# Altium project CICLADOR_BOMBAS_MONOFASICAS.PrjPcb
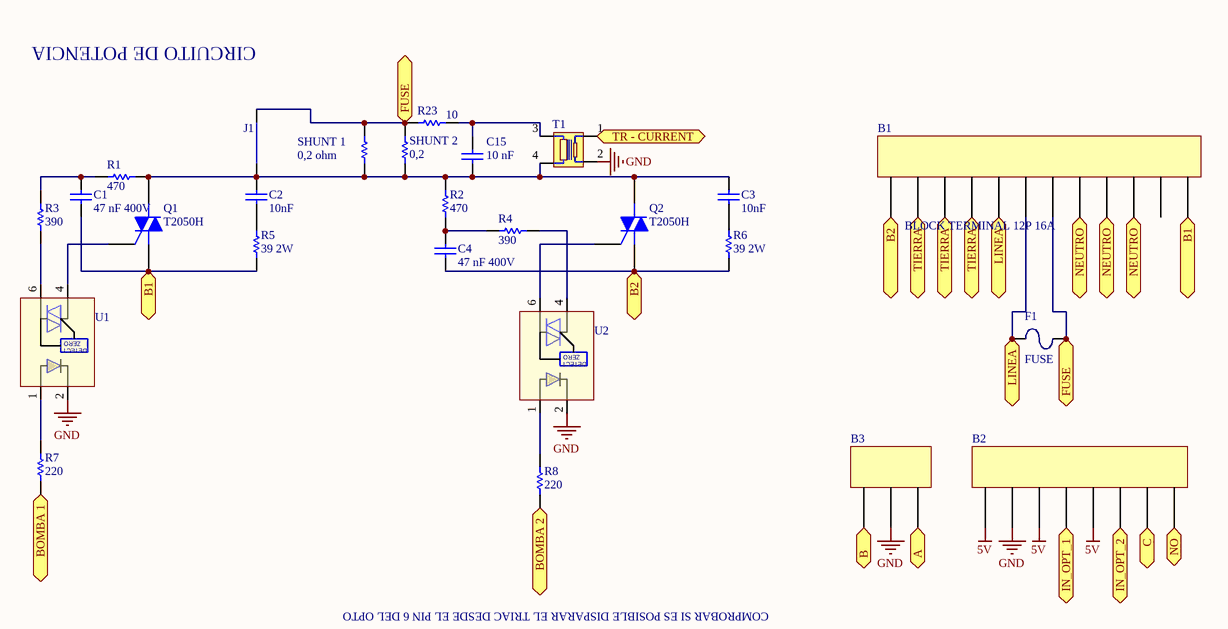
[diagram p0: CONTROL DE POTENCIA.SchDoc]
3 sheets, 80 parts. Net scope: flat (ports and power ports of the same name join across sheets).
Board file: PCB_BOARD_01.PcbDoc
Sheets:
  CONTROL DE POTENCIA.SchDoc
  MCU.SchDoc
  SPERIFERICOS.SchDoc

## Sheet CONTROL DE POTENCIA.SchDoc
size A4

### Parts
B1  BLOCK TERMINAL 12P 16A  [BLOCK TERMINAL 12P 16A]
B2  BLOCK TERMINAL 12P 16A  [BORNERA 8P 2.5MM 2A]  (value not drawn)
B3  BORNERA 3P  [BORNERA_ENCASTRE]  (value not drawn)
C1  value 47 nF 400V  [VP60-3.6]  (hidden comment: 47 nF  400V)
C2  10nF  [VP60-3.6]
C3  10nF  [VP60-3.6]
C4  value 47 nF 400V  [VP60-3.6]  (hidden comment: 47 nF  400V)
C15  10 nF  [0805]
F1  FUSE  [VP45-3.2]
J1  JUMPER  [JUMPER 10MM]  (value not drawn)
Q1  T2050H  [TO254P1280-3_4M]
Q2  T2050H  [TO254P1280-3_4M]
R1  470  [ERA-0805]
R2  470  [ERA-0805]
R3  390  [ERA-0805]
R4  390  [ERA-0805]
R5  39 2W  [R12x4]
R6  39 2W  [R12x4]
R7  220  [ERA-0805]
R8  220  [ERA-0805]
R23  10  [ERA-0805]
SHUNT_1  0,2 ohm  [M1WS-2512]
SHUNT_2  0,2  [M1WS-2512]
T1  TRANSFORMADOR  [TRANSFORMADOR TRANSMISION DE DATOS]  (value not drawn)
U1  MOC3041  [DIP_6]  (value not drawn)
U2  MOC3041  [DIP_6]  (value not drawn)

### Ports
A, B, B1, B2, BOMBA 1, BOMBA 2, C, FUSE, IN_OPT_1, IN_OPT_2, LINEA, NEUTRO, NO, TIERRA, TR - CURRENT

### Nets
5V: B2.4 B2.6 B2.8
GND: B2.7 B3.2 T1.2 U1.2 U2.2
NetB1_1: B1.1 C1.1 Q1.1(M1) R5.1 ; port B1
NetB1_3: B1.3 B1.4 B1.5 ; port NEUTRO
NetB1_6: B1.6 F1.2 J1.2 R23.2 SHUNT_1.1 SHUNT_2.1 ; port FUSE
NetB1_7: B1.7 B1.8 F1.1 ; port LINEA
NetB1_9: B1.9 B1.10 B1.11 ; port TIERRA
NetB1_12: B1.12 C4.1 Q2.1(M1) R6.1 ; port B2
NetB2_1: B2.1 ; port NO
NetB2_2: B2.2 ; port C
NetB2_3: B2.3 ; port IN_OPT_2
NetB2_5: B2.5 ; port IN_OPT_1
NetB3_1: B3.1 ; port A
NetB3_3: B3.3 ; port B
NetC1_2: C1.2 R1.2 R3.1
NetC2_1: C2.1 R5.2
NetC2_2: C2.2 C3.2 C15.1 J1.1 Q1.2(M2) Q2.2(M2) R1.1 R2.1 SHUNT_1.2 SHUNT_2.2 T1.4
NetC3_1: C3.1 R6.2
NetC4_2: C4.2 R2.2 R4.1
NetC15_2: C15.2 R23.1 T1.3
NetL2_2: T1.1 ; port TR - CURRENT
NetQ1_3: Q1.3(G) U1.4
NetQ2_3: Q2.3(G) U2.6
NetR3_2: R3.2 U1.6
NetR4_2: R4.2 U2.4
NetR7_1: R7.1 ; port BOMBA 1
NetR7_2: R7.2 U1.1
NetR8_1: R8.1 ; port BOMBA 2
NetR8_2: R8.2 U2.1

Not connected (* = marked no-connect by the designer): B1 2

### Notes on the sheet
- CIRCUITO DE POTENCIA
- COMPROBAR SI ES POSIBLE DISPARAR EL TRIAC DESDE EL PIN 6 DEL OPTO

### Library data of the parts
C1 C4 = C0805: Ceramic Chip Capacitor - Standard; Note: Footprint corresponds to dimensions for bulk cassette packaging. This case size has tightened tolerances.
C2 C3 = VP52BA102GC: Dipped Radial Multilayer Ceramic Capacitor COG (NPO): 1000pF, 200V; Provider: Mouser
C15 = C0805: Ceramic Chip Capacitor - Standard; Note: Footprint corresponds to dimensions for bulk cassette packaging. This case size has tightened tolerances.; Value: 100nF
F1 = FUSE: Fusible 0697H9200-02 - 20A Slow
J1 = JUMPER: PUENTE
Q1 Q2 = Q8025R5: Triac (25.0 Amps); pin to pad: 2>4
R1-R4 R7 R8 R23 = ERAS: Metal Film Thermosensitive Chip Resistor, 0.56 Ohm to 10k Ohm Range, 5% Tolerance, 0805 Size, 0.1 W; Note: If flow soldering, adjust pad width of PCB Footprint to 0.7 - 0.8 times the width of the resistor.
R5 R6 = ERG2: Metal Oxide Film Resistor, 0.1 Ohm to 100k Ohm Range, 2% and 5% Tolerance, 2 W
SHUNT_1 = ERAS: Metal Film Thermosensitive Chip Resistor, 0.56 Ohm to 10k Ohm Range, 5% Tolerance, 0805 Size, 0.1 W; Note: If flow soldering, adjust pad width of PCB Footprint to 0.7 - 0.8 times the width of the resistor.; Component: Resistor Shunt; Value: 470
SHUNT_2 = ERAS: Metal Film Thermosensitive Chip Resistor, 0.56 Ohm to 10k Ohm Range, 5% Tolerance, 0805 Size, 0.1 W; Note: If flow soldering, adjust pad width of PCB Footprint to 0.7 - 0.8 times the width of the resistor.; Value: 470
T1 = TRANSFORMADOR: pin to pad: 2>3 3>4 4>6
U1 U2 = MOC3021: OPTOACOPLADOR

## Sheet MCU.SchDoc
size A4
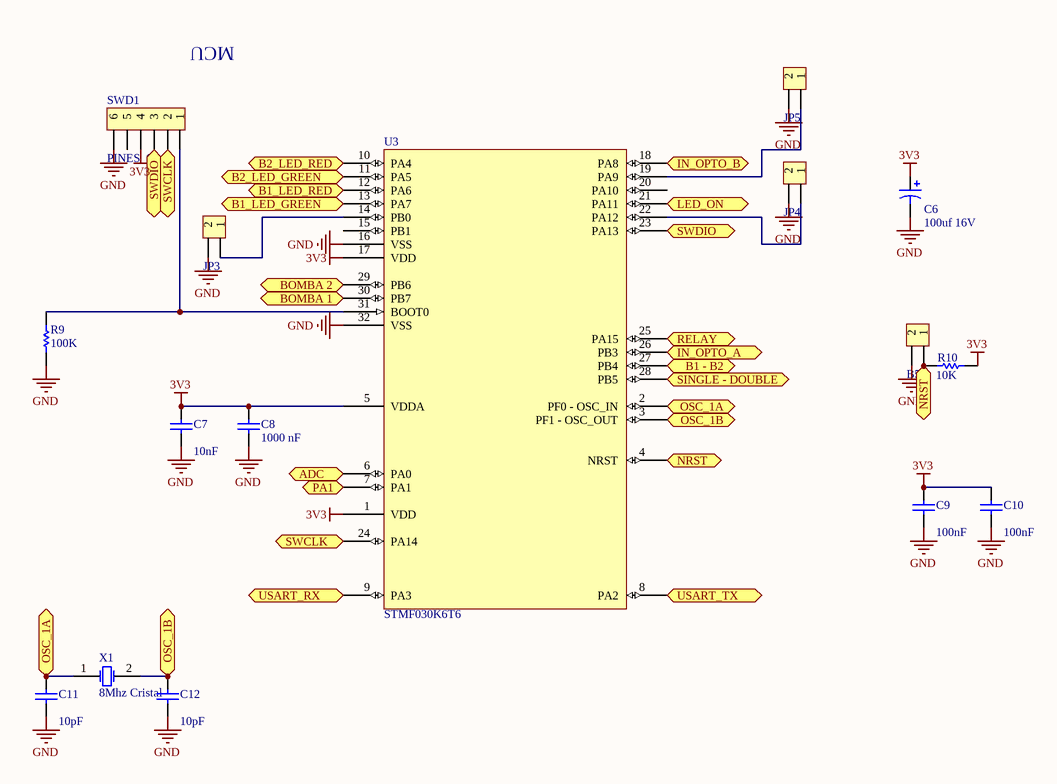
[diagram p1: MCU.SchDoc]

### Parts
B5  PINES_6  [PINES_2_2.54]  (value not drawn)
C6  100uf 16V  [CAPPR2-5X11]
C7  value 10nF  [0805]  (hidden comment: 10 nF)
C8  1000 nF  [0805]
C9  value 100nF  [0805]  (hidden comment: 100 nF)
C10  100nF  [0805]
C11  value 10pF  [0805]  (hidden comment: 10 pF)
C12  value 10pF  [0805]  (hidden comment: 10 pF)
JP3  PINES_6  [PINES_2_2.54]  (value not drawn)
JP4  PINES_6  [PINES_2_2.54]  (value not drawn)
JP5  PINES_6  [PINES_2_2.54]  (value not drawn)
R9  100K  [ERA-0805]
R10  10K  [ERA-0805]
SWD1  PINES_6  [PINES_6_2.54]
U3  STMF030K6T6  [LQFP_32]
X1  8Mhz Cristal  [HC49/4H_SMX]

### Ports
ADC, B1 - B2, B1_LED_GREEN, B1_LED_RED, B2_LED_GREEN, B2_LED_RED, BOMBA 1, BOMBA 2, IN_OPTO_A, IN_OPTO_B, LED_ON, NRST, OSC_1A, OSC_1B, PA1, RELAY, SINGLE - DOUBLE, SWCLK, SWDIO, USART_RX, USART_TX

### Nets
3V3: C6.1 C7.2 C8.2 C9.2 C10.2 R10.2 SWD1.4 U3.1(VDD) U3.5(VDDA) U3.17(VDD)
GND: B5.2 C6.2 C7.1 C8.1 C9.1 C10.1 C11.1 C12.1 JP3.2 JP4.2 JP5.2 R9.1 SWD1.6 U3.16(VSS) U3.32(VSS)
NetB5_1: B5.1 R10.1 U3.4(NRST) ; port NRST
NetC11_2: C11.2 U3.2(PF0_-_OSC_IN) X1.1(OSC1) ; port OSC_1A
NetC12_2: C12.2 U3.3(PF1_-_OSC_OUT) X1.2(OSC2) ; port OSC_1B
NetC13_2: U3.6(PA0) ; port ADC
NetJP1_1: U3.28(PB5) ; port SINGLE - DOUBLE
NetJP2_1: U3.27(PB4) ; port B1 - B2
NetJP3_1: JP3.1 U3.14(PB0)
NetJP4_1: JP4.1 U3.22(PA12)
NetJP5_1: JP5.1 U3.19(PA9)
NetQ5_2: U3.25(PA15) ; port RELAY
NetR7_1: U3.30(PB7) ; port BOMBA 1
NetR8_1: U3.29(PB6) ; port BOMBA 2
NetR9_2: R9.2 SWD1.1 U3.31(BOOT0)
NetR18_1: U3.13(PA7) ; port B1_LED_GREEN
NetR19_1: U3.10(PA4) ; port B2_LED_RED
NetR20_1: U3.12(PA6) ; port B1_LED_RED
NetR21_1: U3.11(PA5) ; port B2_LED_GREEN
NetR24_2: U3.7(PA1) ; port PA1
NetR_1: U3.21(PA11) ; port LED_ON
NetSWD1_2: SWD1.2 U3.24(PA14) ; port SWCLK
NetSWD1_3: SWD1.3 U3.23(PA13) ; port SWDIO
NetU3_8: U3.8(PA2) ; port USART_TX
NetU3_9: U3.9(PA3) ; port USART_RX
NetU3_18: U3.18(PA8) ; port IN_OPTO_B
NetU3_26: U3.26(PB3) ; port IN_OPTO_A

Not connected (* = marked no-connect by the designer): SWD1 5; U3 15(PB1) 20(PA10)

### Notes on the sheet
- MCU

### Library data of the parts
B5 JP3-JP5 SWD1 = PINES_6: 6 Pines - 2.54 mm
C6 = 94SL106X0016CBP: CAPACITOR ELECTROLITICO RADIAL; Note: Part Numbers shown are for ± 20% capacitance tolerance (X0).; PCB_Layout: Complies with Manufacturer's Recommendation.; DrillSize: Nominal, Rounded to the nearest 0.1mm; Value: 10uF
C7 C9-C12 = C0805: as C1 on sheet CONTROL DE POTENCIA
C8 = C0805: as C15 on sheet CONTROL DE POTENCIA
R9 R10 = ERAS: as R1 on sheet CONTROL DE POTENCIA
X1 = HC49/4H_SMX: Surface Mount Quartz Crystal; Note: PCB layout complies with manufacturer's recommendation.

## Sheet SPERIFERICOS.SchDoc
size A4
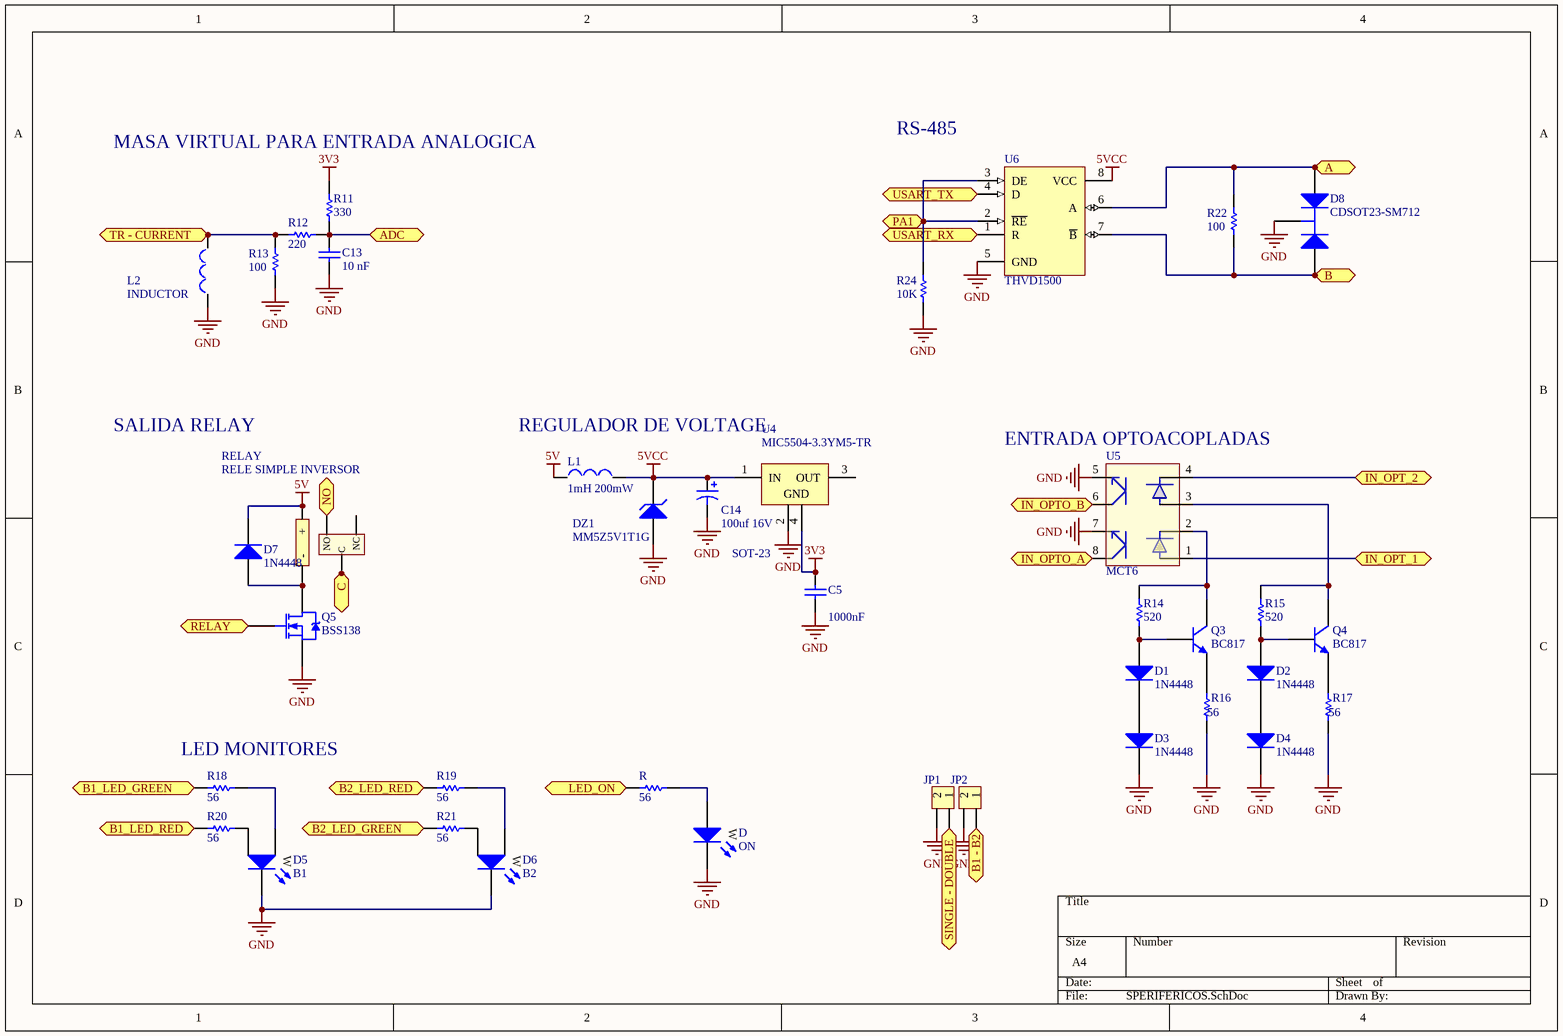
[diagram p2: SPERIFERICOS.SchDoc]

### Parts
C5  value 1000nF  [0805]  (hidden comment: 0)
C13  10 nF  [0805]
C14  100uf 16V  [CAPPR2-5X11]
D  ON  [LED]
D1  1N4448  [SOD-323]
D2  1N4448  [SOD-323]
D3  1N4448  [SOD-323]
D4  1N4448  [SOD-323]
D5  B1  [LED_BICOLOR]
D6  B2  [LED_BICOLOR]
D7  1N4448  [SOD-323]
D8  CDSOT23-SM712  [SOT-323]
DZ1  MM5Z5V1T1G  [SOD323]
JP1  PINES_6  [PINES_2_2.54]  (value not drawn)
JP2  PINES_6  [PINES_2_2.54]  (value not drawn)
L1  1mH 200mW  [CAPPR5-10X12.5]
L2  INDUCTOR  [AC1015]
Q3  BC817  [SOT23-3M]
Q4  BC817  [SOT23-3M]
Q5  BSS138  [SOT23-3M]
R  value 56  [ERA-0805]  (hidden comment: 56 ohm)
R11  330  [ERA-0805]
R12  220  [ERA-0805]
R13  100  [ERA-0805]
R14  520  [ERA-0805]
R15  520  [ERA-0805]
R16  value 56  [ERA-0805]  (hidden comment: 56 ohm)
R17  value 56  [ERA-0805]  (hidden comment: 56 ohm)
R18  value 56  [ERA-0805]  (hidden comment: 56 ohm)
R19  value 56  [ERA-0805]  (hidden comment: 56 ohm)
R20  value 56  [ERA-0805]  (hidden comment: 56 ohm)
R21  value 56  [ERA-0805]  (hidden comment: 56 ohm)
R22  100  [ERA-0805]
R24  10K  [ERA-0805]
RELAY  RELE SIMPLE INVERSOR  [RELAY NT78]
U4  MIC5504-3.3YM5-TR  Encapsulado: SOT-23  [SOT23-5AM]
U5  MCT6  [S-DIP-8]
U6  THVD1500  [D008_N]

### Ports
A, ADC, B, B1 - B2, B1_LED_GREEN, B1_LED_RED, B2_LED_GREEN, B2_LED_RED, C, IN_OPT_1, IN_OPT_2, IN_OPTO_A, IN_OPTO_B, LED_ON, NO, PA1, RELAY, SINGLE - DOUBLE, TR - CURRENT, USART_RX, USART_TX

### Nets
3V3: C5.2 R11.2 U4.4(GND)
5V: D7.2(K) L1.1 RELAY.1(+)
5VCC: C14.1 DZ1.2(K) L1.2 U4.1(IN) U6.8(VCC)
GND: C5.1 C13.1 C14.2 D.2(K) D3.2(K) D4.2(K) D5.2(K) D6.2(K) D8.3(K) DZ1.1(A) JP1.2 JP2.2 L2.1 Q5.3(S) R13.1 R16.2 R17.2 R24.1 U4.2(GND) U5.5 U5.7 U6.5(GND)
NetB2_1: RELAY.4(NO) ; port NO
NetB2_3: U5.4 ; port IN_OPT_2
NetB2_5: U5.1 ; port IN_OPT_1
NetB3_1: D8.2(A2) R22.2 U6.6(A) ; port A
NetB3_3: D8.1(A1) R22.1 U6.7(~{B}) ; port B
NetC13_2: C13.2 R11.1 R12.2 ; port ADC
NetD1_1: D1.1(A) Q3.1(B) R14.2
NetD1_2: D1.2(K) D3.1(A)
NetD2_1: D2.1(A) Q4.1(B) R15.2
NetD2_2: D2.2(K) D4.1(A)
NetD5_1: D5.1(A) R18.2
NetD5_3: D5.3(A) R20.2
NetD6_1: D6.1(A) R19.2
NetD6_3: D6.3(A) R21.2
NetD7_1: D7.1(A) Q5.1(D) RELAY.2(-)
NetD_1: D.1(A) R.2
NetJP1_1: JP1.1 ; port SINGLE - DOUBLE
NetJP2_1: JP2.1 ; port B1 - B2
NetL2_2: L2.2 R12.1 R13.2 ; port TR - CURRENT
NetQ3_2: Q3.2(E) R16.1
NetQ3_3: Q3.3(C) R14.1 U5.2
NetQ4_2: Q4.2(E) R17.1
NetQ4_3: Q4.3(C) R15.1 U5.3
NetQ5_2: Q5.2(G) ; port RELAY
NetR18_1: R18.1 ; port B1_LED_GREEN
NetR19_1: R19.1 ; port B2_LED_RED
NetR20_1: R20.1 ; port B1_LED_RED
NetR21_1: R21.1 ; port B2_LED_GREEN
NetR24_2: R24.2 U6.2(~{RE}) U6.3(DE) ; port PA1
NetR_1: R.1 ; port LED_ON
NetU3_8: U6.4(D) ; port USART_TX
NetU3_9: U6.1(R) ; port USART_RX
NetU3_18: U5.6 ; port IN_OPTO_B
NetU3_26: U5.8 ; port IN_OPTO_A

Not connected (* = marked no-connect by the designer): RELAY 3(C) 5(NC); U4 3(OUT)

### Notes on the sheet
- (near R11) MASA VIRTUAL PARA ENTRADA ANALOGICA
- RS-485
- SALIDA RELAY
- REGULADOR DE VOLTAGE
- (near U5) ENTRADA OPTOACOPLADAS
- (near R18) LED MONITORES

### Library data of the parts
C5 C13 = C0805: as C1 on sheet CONTROL DE POTENCIA
C14 = 94SL106X0016CBP: as C6 on sheet MCU
D = LED
D1-D4 D7 = 1N4044: 275 Amp Avg Power Silicon Rectifier Diode; pin to pad: 1>2 2>1; Note: No PCB Footprint Available
D5 D6 = LED_BICOLOR_CC: Led bicolor catodo comun
D8 = BAR64-05W: PIN Diode for RF switches (High Isolation)
DZ1 = 1N968B: Half Watt Zener; pin to pad: 1>2 2>1
JP1 JP2 = PINES_6: 6 Pines - 2.54 mm
L1 L2 = INDUCTOR: INDUCTOR SMD
Q3 Q4 = BC817-16LT1: General Purpose Transistor NPN Silicon
Q5 = IRF5NJZ48: HEXFET Power MOSFET
R R11-R22 R24 = ERAS: as R1 on sheet CONTROL DE POTENCIA
U4 = MC33275ST-5.0T3: Low Dropout 300mA Voltage Regulator; pin to pad: 4>5
U5 = PC827: OPTOACOPLADOR
U6 = TL3695D: Differential Bus Transceiver; Note: Receiver Hysteresis typically 70mV.

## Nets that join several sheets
3V3: MCU (10 pins), SPERIFERICOS (C5.2 R11.2 U4.4)
5V: CONTROL DE POTENCIA (B2.4 B2.6 B2.8), SPERIFERICOS (D7.2 L1.1 RELAY.1)
GND: CONTROL DE POTENCIA (5 pins), MCU (15 pins), SPERIFERICOS (22 pins)
NetB2_1: CONTROL DE POTENCIA (B2.1), SPERIFERICOS (RELAY.4)
NetB2_3: CONTROL DE POTENCIA (B2.3), SPERIFERICOS (U5.4)
NetB2_5: CONTROL DE POTENCIA (B2.5), SPERIFERICOS (U5.1)
NetB3_1: CONTROL DE POTENCIA (B3.1), SPERIFERICOS (D8.2 R22.2 U6.6)
NetB3_3: CONTROL DE POTENCIA (B3.3), SPERIFERICOS (D8.1 R22.1 U6.7)
NetC13_2: MCU (U3.6), SPERIFERICOS (C13.2 R11.1 R12.2)
NetJP1_1: MCU (U3.28), SPERIFERICOS (JP1.1)
NetJP2_1: MCU (U3.27), SPERIFERICOS (JP2.1)
NetL2_2: CONTROL DE POTENCIA (T1.1), SPERIFERICOS (L2.2 R12.1 R13.2)
NetQ5_2: MCU (U3.25), SPERIFERICOS (Q5.2)
NetR7_1: CONTROL DE POTENCIA (R7.1), MCU (U3.30)
NetR8_1: CONTROL DE POTENCIA (R8.1), MCU (U3.29)
NetR18_1: MCU (U3.13), SPERIFERICOS (R18.1)
NetR19_1: MCU (U3.10), SPERIFERICOS (R19.1)
NetR20_1: MCU (U3.12), SPERIFERICOS (R20.1)
NetR21_1: MCU (U3.11), SPERIFERICOS (R21.1)
NetR24_2: MCU (U3.7), SPERIFERICOS (R24.2 U6.2 U6.3)
NetR_1: MCU (U3.21), SPERIFERICOS (R.1)
NetU3_8: MCU (U3.8), SPERIFERICOS (U6.4)
NetU3_9: MCU (U3.9), SPERIFERICOS (U6.1)
NetU3_18: MCU (U3.18), SPERIFERICOS (U5.6)
NetU3_26: MCU (U3.26), SPERIFERICOS (U5.8)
